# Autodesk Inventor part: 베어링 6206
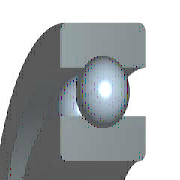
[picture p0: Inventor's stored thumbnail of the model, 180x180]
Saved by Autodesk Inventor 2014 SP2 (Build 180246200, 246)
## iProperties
Created: 2009-02
Part Number: 베어링 6206
Material: Steel, Mild
Description: 깊은 그루브 볼 베어링
Document SubType Name: Modeling
Standard: KS B 2023
Designer: KYOUNG IL JANG
Standards Organization: KS
Language: ko-KR
Size Designation: 6206 - 30 x 62 x 16
Categories: <MemberInstance><Categories><Category DisplayName="샤프트 부품" InternalName="7f7aeb1f-a693-4053-b835-cee3144e0d98" Mnemonic="SHFT"><Category DisplayName="베어링" Inter
Density: 1 g/cm^3
Appearance: Metal-Steel
Company: 한국ATC센터
IsCustomPart: 0
Author: KYOUNG IL JANG
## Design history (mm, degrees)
sketch "스케치" dims "d0" = 8.32 (= -0.26 x WD + 0.26 x BD)
  geometry: L1 (3.84, 23)-(12.16, 23); L2 (8, 23)-(8, 18.84); L3 (8, 23)-(8, 27.16); L4 (4.909, 20.216)-(0, 20.216); L5 (0, 15)-(16, 15); L6 (4.909, 25.784)-(0, 25.784); L7 (0, 31)-(16, 31); L8 (16, 15)-(16, 20.216); L9 (11.091, 20.216)-(16, 20.216); L10 (11.091, 25.784)-(16, 25.784); L11 (16, 31)-(16, 25.784); L12 (-1.4, 0)-(8.4, 0) reference; L13 (0, -0.3)-(0, 5.3) reference
  constraints: 22 end point, 4 point on line, 2 collinear, 2 perpendicular, 2 symmetric about line, 1 midpoint, 1 parallel, 14 other
  dimensions: "d9" = 30 diameter of L5 L12 (= WD); "d11" = 62 diameter of L7 L12 (= BD); "d12" = 16 distance between parallel lines of L8 L13 (= KB); "d13" = 40.432 diameter of L9 L12 (= 0.326 x BD + 0.674 x WD)
revolve "본체" stored, may be unused: angle "d6" = 90 deg
revolve "볼" stored, may be unused: angle "d7" = 90 deg
pattern_circular "IDS_ARRAYBALL[SIMPL:T]" dims angle "d3" = 360 deg
body "Solid1"
fillet "모깎기1" dims "d1" = 1 (= KRS)
other parameters: "WD" = 30 [user parameter; used in 5 equation terms], "BD" = 62 [user parameter; used in 5 equation terms], "KB" = 16 [user parameter; used in 1 equation term], "KRS" = 1 [user parameter; used in 1 equation term], "d4" = 0, "d5" = 0, "d8" = 0, "d14" = 0, "d15" = 0, "BBA" = 0 [user parameter], "BC0" = 1.12e+07 [user parameter], "BC" = 1.95e+07 [user parameter], "BR" = 31 (= 0.5 x BD) [user parameter], "WR" = 15 (= 0.5 x WD) [user parameter]
